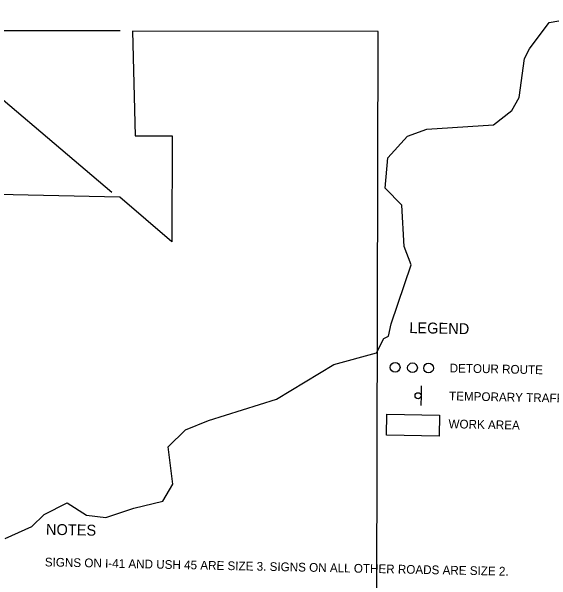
# Model space of a CAD drawing. Extents: x 331323 to 388339, y 121519 to 205315.
# Drawn here: x 365285 to 369003, y 128453 to 132368 of the extents above; entities that cross this region are included whole.
import ezdxf

# ---------------------------------------------------------------- set-up
doc = ezdxf.new("R2010")
doc.units = 0
for name, color, linetype in [('CA-TEXT', 7, 'Continuous'), ('CE-TOPO-CONC-SLAB', 7, 'Continuous'), ('Level 2', 7, 'Continuous'), ('Level 21', 7, 'Continuous'), ('Level 4', 7, 'Continuous'), ('Level 57', 7, 'Continuous'), ('P_TC', 7, 'Continuous'), ('SIGNS-POLES', 7, 'Continuous')]:
    doc.layers.add(name, color=color, linetype=linetype)

msp = doc.modelspace()

# ---------------------------------------------------------------- linework, layer by layer
at = {"layer": 'CE-TOPO-CONC-SLAB'}
for centre in [(367925.9, 129919.1), (368045.2, 129916.7), (368155.8, 129914.5)]:
    msp.add_circle(centre, 33.5, dxfattribs=at)
at = {"layer": 'Level 2'}
msp.add_lwpolyline([(362656.9, 133359.5), (363064.7, 133262.1), (364310.7, 132725.8), (364525.6, 132507.2), (364582.7, 132373.4), (364830.3, 132096.1), (365977.2, 131123.9)], dxfattribs=at)
at = {"layer": 'Level 21'}
msp.add_lwpolyline([(375076, 132102.1), (370942.7, 132184.5), (370894.9, 130740.5), (370391.8, 130742.4), (370319, 126443.1), (367794.6, 126431), (367808.5, 132230.6), (366119.6, 132232.6), (366135.9, 131512.6), (366392.2, 131511.6), (366389.5, 130783.4), (366030.6, 131090.7), (365085.3, 131111.7), (365089.7, 131495.3), (364322.8, 131506.6), (364297.4, 130439.9), (364588.5, 130440.1), (364573.4, 129673), (363928.9, 129678.5), (363911.7, 128375.4), (362625.6, 128409.6), (362593.8, 121807)], dxfattribs=at)
at = {"layer": 'Level 4'}
msp.add_lwpolyline([(363947.6, 132237.5), (366034.8, 132236.3)], dxfattribs=at)
at = {"layer": 'Level 57'}
msp.add_lwpolyline([(365241.4, 128742.3), (365425.6, 128824), (365509.8, 128906.6), (365669, 128988.4), (365801.7, 128903.9), (365934.9, 128886), (366127.3, 128951), (366328, 128999.1), (366395.7, 129115.2), (366364.8, 129373.8), (366482.6, 129489.4), (366641.7, 129554.7), (367110, 129700.4), (367504.2, 129938.5), (367796.9, 130019.2), (367847.8, 130118.8), (367881.3, 130135.1), (367898.8, 130218.3), (368036, 130625.4), (367987.1, 130750.8), (367973, 131034.3), (367857.3, 131152), (367875.9, 131360.2), (368010.8, 131509), (368144.6, 131557.8), (368603.6, 131587), (368729.6, 131685.8), (368780.5, 131777), (368816.3, 132043.4), (368850.3, 132109.7), (368985.4, 132291.8), (369119.1, 132315.6)], dxfattribs=at)
at = {"layer": 'P_TC'}
msp.add_lwpolyline([(367868.5, 129598.4), (368232.1, 129591.1), (368229.2, 129446.1), (367865.6, 129453.4)], close=True, dxfattribs=at)
at = {"layer": 'SIGNS-POLES'}
for p, q in [((368105.2, 129793.1), (368104.9, 129725.6)), ((368104.4, 129725.1), (368103.5, 129657.6))]:
    msp.add_line(p, q, dxfattribs=at)
msp.add_circle((368083.6, 129724.6), 20.9, dxfattribs=at)

# ---------------------------------------------------------------- texts
at = {"layer": 'CA-TEXT'}
for s, height, rotation, p in [('LEGEND', 75, 358.8468, (368022.9, 130155.6)), ('DETOUR ROUTE', 60, 358.8468, (368300.5, 129885.2)), ('TEMPORARY TRAFFIC CONTROL SIGN POST', 60, 358.8468, (368296.6, 129693.2)), ('WORK AREA', 60, 358.8468, (368292.7, 129501.3)), ('NOTES', 75, 358.8468, (365522.4, 128768.4)), ('SIGNS ON I-41 AND USH 45 ARE SIZE 3. SIGNS ON ALL OTHER ROADS ARE SIZE 2.', 60, 358.8462, (365514.9, 128550.7))]:
    msp.add_text(s, height=height, rotation=rotation, dxfattribs=at).set_placement(p)

doc.saveas('drawing.dxf')
